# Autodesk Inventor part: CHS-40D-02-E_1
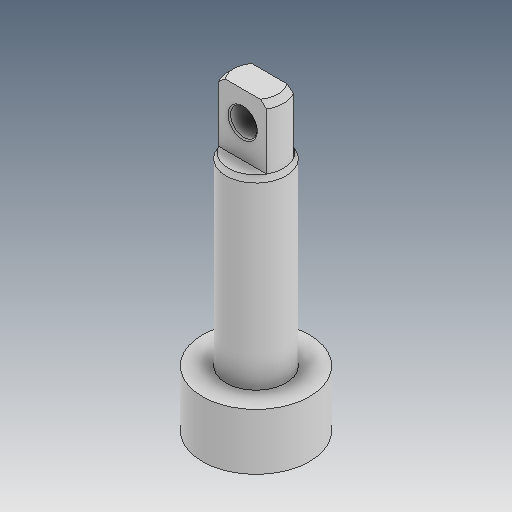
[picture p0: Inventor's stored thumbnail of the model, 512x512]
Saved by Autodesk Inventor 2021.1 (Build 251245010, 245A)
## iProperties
Created: 2019-04
Part Number: CHS-40D-02-E_1
Material: Ogólny
Document SubType Name: Modeling
Designer: user
Density: 1 g/cm^3
Appearance: Domyślna
Author: user
Revision Number: ÈÎºÎ
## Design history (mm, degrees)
feature "ÊäÈë1"
feature "ÊäÈë2"
node "Bryła1"
node "Bryła2"
